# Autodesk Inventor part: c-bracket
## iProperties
Created: 2006-04
Part Number: c-bracket
Document SubType Name: Modeling
Designer: E. MOSS
Author: E. MOSS
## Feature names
1. Extrusion1
2. Extrusion2
3. Extrusion3
4. Extrusion4
5. Extrusion5
6. Mirror1
7. Fillet1
8. Extrusion7
9. Hole1
10. texture [Extrusion]
